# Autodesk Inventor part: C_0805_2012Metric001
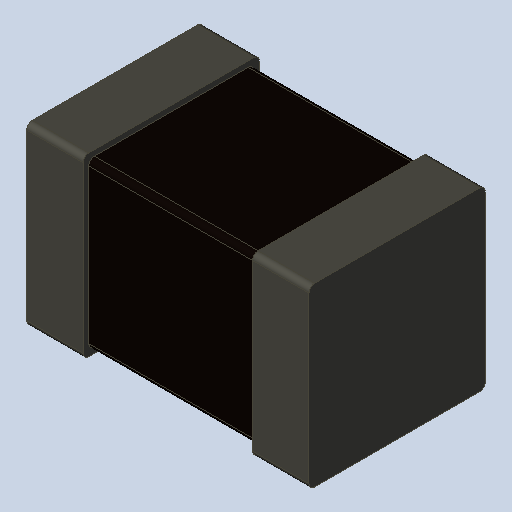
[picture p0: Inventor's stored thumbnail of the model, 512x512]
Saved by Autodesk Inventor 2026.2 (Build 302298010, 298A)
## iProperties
Created: 2026-10
Part Number: C_0805_2012Metric001
Material: Générique
Document SubType Name: Modeling
Designer: mel
Density: 1 g/cm^3
Appearance: Par défaut
Author: mel
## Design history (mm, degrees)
feature "Base1"
node "Solide1"
